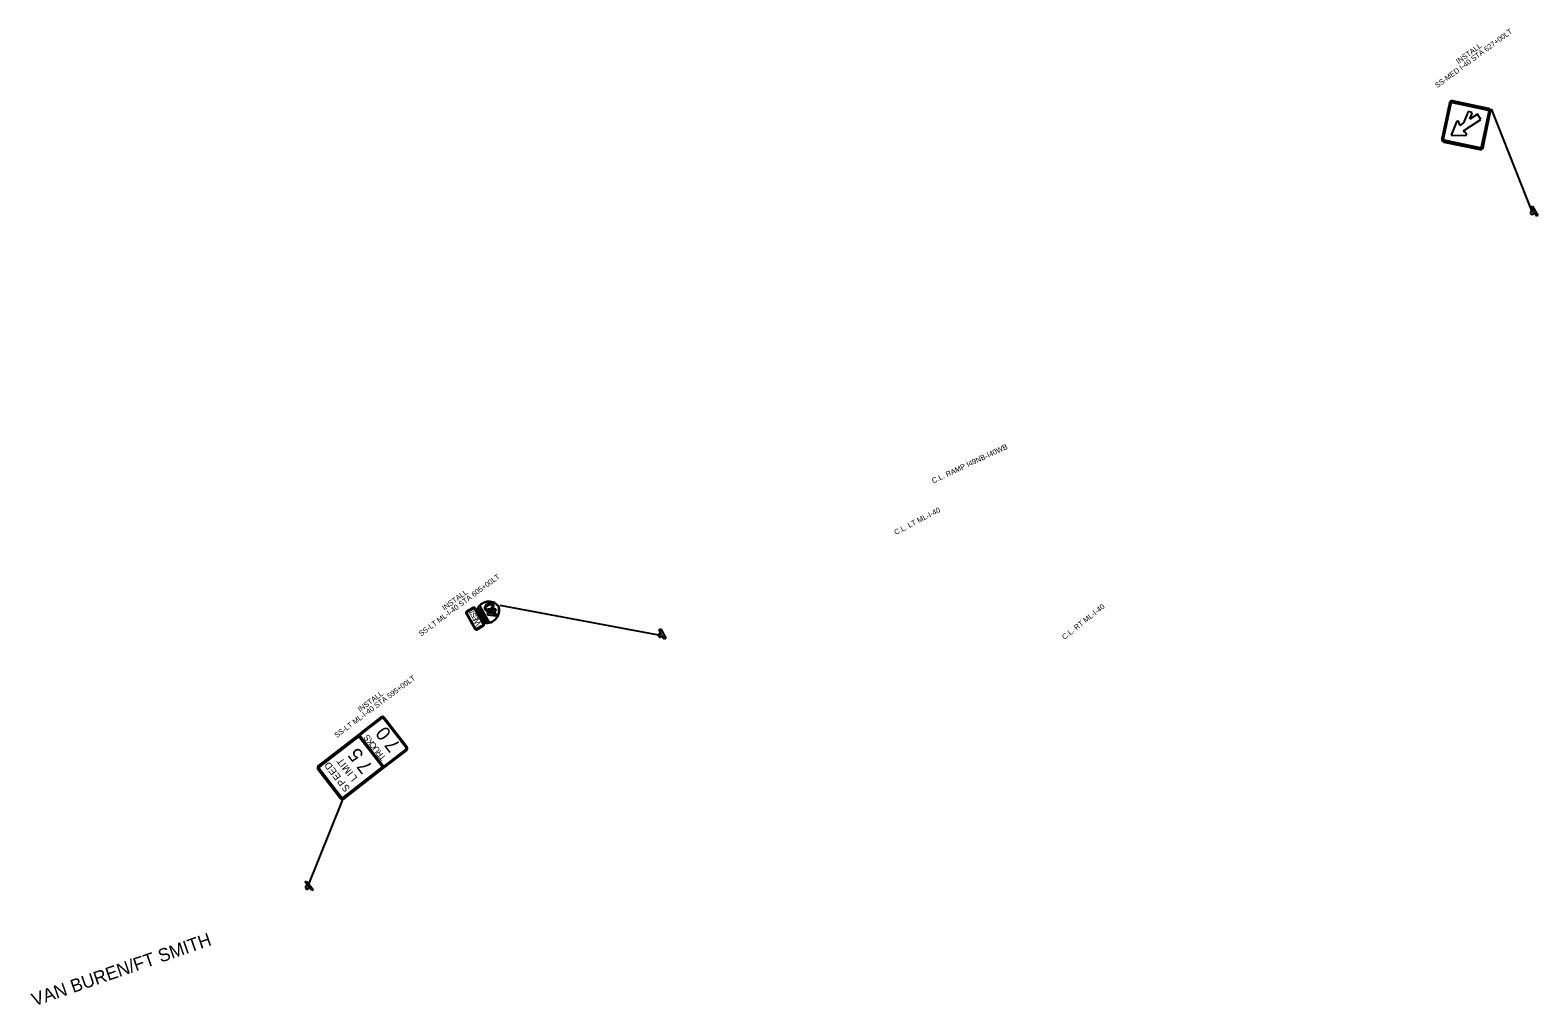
# Model space of a CAD drawing. Extents: x 639753 to 654136, y 407791 to 434220.
# Drawn here: x 639753 to 643194, y 422989 to 425213 of the extents above; entities that cross this region are included whole.
import ezdxf

# ---------------------------------------------------------------- set-up
doc = ezdxf.new("R2010")
doc.units = 0
for name, color, linetype in [('C-TRAF-SYMB', 7, 'Continuous'), ('R_Anno_Text', 7, 'Continuous'), ('R_Dimension', 7, 'Continuous'), ('S_SIGN', 7, 'Continuous')]:
    doc.layers.add(name, color=color, linetype=linetype)

msp = doc.modelspace()

# ---------------------------------------------------------------- linework, layer by layer
at = {"layer": 'C-TRAF-SYMB'}
for p, q in [((643178.4, 424809.3), (643181.8, 424811.3)), ((643183.9, 424799.8), (643178.4, 424809.3)), ((643181.8, 424811.3), (643193.9, 424790.6)), ((643183.8, 424799.7), (643183.9, 424799.8)), ((643190.5, 424788.6), (643184.8, 424798.2)), ((643184.8, 424798.2), (643184.8, 424798.2)), ((643193.9, 424790.6), (643190.5, 424788.6)), ((641188.4, 423844.7), (641191.9, 423846.7)), ((641193.8, 423835.1), (641188.4, 423844.7)), ((641191.9, 423846.7), (641203.6, 423825.7)), ((641193.7, 423835), (641193.8, 423835.1)), ((641194.7, 423833.5), (641194.6, 423833.5)), ((641200.1, 423823.8), (641194.7, 423833.5)), ((641203.6, 423825.7), (641200.1, 423823.8)), ((640380.5, 423268.7), (640383.7, 423271.2)), ((640387.4, 423260), (640380.5, 423268.7)), ((640383.7, 423271.2), (640398.5, 423252.3)), ((640387.3, 423259.9), (640387.4, 423260)), ((640388.5, 423258.6), (640388.4, 423258.5)), ((640395.3, 423249.8), (640388.5, 423258.6)), ((640398.5, 423252.3), (640395.3, 423249.8))]:
    msp.add_line(p, q, dxfattribs=at)
for centre, start, end in [((643181, 424796.9), 120.2947, 17.9748), ((643181, 424796.9), 44.1568, 120.2947), ((641190.8, 423832.3), 119.2135, 16.8936), ((641190.8, 423832.3), 43.0756, 119.2135), ((640384.8, 423256.8), 128.0671, 25.7472), ((640384.8, 423256.8), 51.9292, 128.0671)]:
    msp.add_arc(centre, 4, start, end, dxfattribs=at)
at = {"layer": 'R_Dimension'}
for p, q in [((643087.3, 425033.5), (643181, 424796.9)), ((640824.5, 423900.7), (641190.8, 423832.3)), ((640464.4, 423455.4), (640384.8, 423256.8))]:
    msp.add_line(p, q, dxfattribs=at)
at = {"layer": 'S_SIGN'}
for p, q in [((642992.1, 425047.4), (642974.8, 424965.2)), ((643081.4, 425034.7), (642999.3, 425052)), ((643008.6, 425004), (642996.1, 424974)), ((643016.3, 424995.5), (643013.8, 425003.7)), ((643024, 424983.8), (643063.6, 425009.6)), ((643043.9, 425025.5), (643034.6, 425027.5)), ((643056, 425021.4), (643039, 425010.3)), ((643063.6, 425009.6), (643056, 425021.4)), ((643068.8, 424945.4), (643086.1, 425027.6)), ((642996.1, 424974), (643028.6, 424973.3)), ((643017.8, 424996.5), (643016.3, 424995.5)), ((643030.4, 424978.2), (643024, 424983.8)), ((642979.5, 424958.1), (643061.7, 424940.8)), ((640747.2, 423882.9), (640767.7, 423846.2)), ((640764.1, 423895.7), (640748.4, 423886.9)), ((640788.7, 423857.9), (640768.2, 423894.6)), ((640778.6, 423899.5), (640799.8, 423861.6)), ((640800.8, 423861.8), (640779.3, 423900.2)), ((640771.8, 423845), (640787.5, 423853.8))]:
    msp.add_line(p, q, dxfattribs=at)
for points in [[(642993.6, 425047.1), (642976.3, 424964.9)], [(642978.7, 424964.4), (642996.1, 425046.6)], [(642993.6, 425047.1), (642993.6, 425047.1), (642993.6, 425047.1)], [(642998.4, 425048.1), (643080.6, 425030.8)], [(643081.1, 425033.2), (642998.9, 425050.5)], [(643082.2, 425028.4), (643064.9, 424946.2)], [(643067.3, 424945.7), (643084.6, 425027.9)], [(643081.1, 425033.2), (643081.1, 425033.2), (643081.1, 425033.2)], [(642979.8, 424959.5), (643062, 424942.2)], [(642979.8, 424959.5), (642979.8, 424959.5), (642979.8, 424959.5)], [(643062.5, 424944.7), (642980.3, 424962)], [(643067.3, 424945.7), (643067.3, 424945.7), (643067.3, 424945.7)], [(640796.4, 423903.4), (640793.8, 423901.7), (640791.6, 423899.7), (640790.3, 423897.8), (640789.7, 423895.7), (640789.8, 423893.4), (640790.6, 423891.3), (640792, 423889.5), (640793.8, 423888.3), (640796, 423887.7), (640798.2, 423887.8), (640801.1, 423888.7), (640803.9, 423890), (640806.5, 423891.7), (640808.8, 423893.7), (640810, 423895.6), (640810.6, 423897.7), (640810.6, 423899.9), (640809.8, 423902.1), (640808.4, 423903.8), (640806.5, 423905.1), (640804.4, 423905.7), (640802.2, 423905.6), (640799.3, 423904.7), (640796.4, 423903.4)], [(640792, 423889.5), (640793.8, 423888.3), (640796, 423887.7), (640798.2, 423887.8), (640801.1, 423888.7), (640803.9, 423890), (640806.5, 423891.7), (640808.8, 423893.7), (640810, 423895.6), (640810.6, 423897.7), (640810.6, 423899.9), (640809.8, 423902.1), (640808.4, 423903.8), (640806.5, 423905.1), (640804.4, 423905.7), (640802.2, 423905.6), (640799.3, 423904.7), (640796.4, 423903.4), (640793.8, 423901.7), (640791.6, 423899.7), (640790.3, 423897.8), (640789.7, 423895.7), (640789.8, 423893.4), (640790.6, 423891.3), (640792, 423889.5)], [(640798.1, 423900.5), (640800.5, 423901.6), (640802.9, 423902.3), (640804.1, 423902.4), (640805.2, 423902.1), (640806.2, 423901.4), (640806.9, 423900.5), (640807.3, 423899.5), (640807.4, 423898.6), (640807.2, 423897.6), (640806.8, 423896.7), (640806.1, 423895.7), (640805.1, 423894.8), (640803.9, 423893.8), (640802.3, 423892.9), (640799.9, 423891.8), (640797.4, 423891.1), (640796.3, 423891), (640795.2, 423891.3), (640794.2, 423892), (640793.5, 423893), (640793.1, 423893.9), (640793, 423894.9), (640793.1, 423895.8), (640793.6, 423896.7), (640794.3, 423897.7), (640795.3, 423898.6), (640796.5, 423899.6), (640798.1, 423900.5)], [(640798.1, 423900.5), (640800.5, 423901.6), (640802.9, 423902.3), (640804.1, 423902.4), (640805.2, 423902.1), (640806.2, 423901.4), (640806.9, 423900.5), (640807.3, 423899.5), (640807.4, 423898.6), (640807.2, 423897.6), (640806.8, 423896.7), (640806.1, 423895.7), (640805.1, 423894.8), (640803.9, 423893.8), (640802.3, 423892.9), (640799.9, 423891.8), (640797.4, 423891.1), (640796.3, 423891), (640795.2, 423891.3), (640794.2, 423892), (640793.5, 423893), (640793.1, 423893.9), (640793, 423894.9), (640793.1, 423895.8), (640793.6, 423896.7), (640794.3, 423897.7), (640795.3, 423898.6), (640796.5, 423899.6), (640798.1, 423900.5)], [(640747.9, 423883.2), (640768.4, 423846.6)], [(640747.9, 423883.2), (640747.9, 423883.2), (640747.9, 423883.2)], [(640764.5, 423895.1), (640748.8, 423886.3)], [(640769.5, 423847.2), (640749, 423883.8)], [(640749.4, 423885.2), (640765.1, 423894)], [(640764.5, 423895.1), (640764.5, 423895.1), (640764.5, 423895.1)], [(640766.4, 423893.6), (640786.9, 423856.9)], [(640788, 423857.5), (640767.5, 423894.2)], [(640780.7, 423893.7), (640781.9, 423891.5), (640777.5, 423889), (640776.4, 423891.1), (640777, 423891.5), (640777.8, 423890), (640778.9, 423890.6), (640778.4, 423891.5), (640779, 423891.9), (640779.5, 423890.9), (640780.9, 423891.7), (640780.1, 423893.3), (640780.7, 423893.7)], [(640778.5, 423888.6), (640779, 423887.8), (640782.8, 423890), (640783.1, 423889.3), (640779.3, 423887.2), (640779.7, 423886.4), (640779.2, 423886.1), (640778, 423888.3), (640778.5, 423888.6)], [(640783.7, 423888.3), (640784, 423887.7), (640783, 423886.7), (640783.5, 423885.8), (640784.8, 423886.2), (640785.2, 423885.6), (640780.2, 423884.2), (640779.9, 423884.8), (640783.7, 423888.3)], [(640781.6, 423883.2), (640782, 423882.4), (640785.8, 423884.5), (640786.1, 423883.9), (640782.3, 423881.8), (640782.8, 423881), (640782.2, 423880.7), (640781, 423882.9), (640781.6, 423883.2)], [(640782.5, 423886.2), (640781.4, 423885.2), (640782.8, 423885.6), (640782.5, 423886.2)], [(640787, 423879.3), (640786.7, 423879.9), (640786.8, 423880), (640786.9, 423880.1), (640787, 423880.1), (640787.1, 423880.2), (640787.1, 423880.3), (640787.2, 423880.4), (640787.2, 423880.5), (640787.2, 423880.6), (640787.2, 423880.7), (640787.1, 423880.8), (640787.1, 423880.9), (640787, 423881), (640787, 423881.1), (640786.9, 423881.1), (640786.8, 423881.2), (640786.7, 423881.2), (640786.6, 423881.3), (640786.5, 423881.3), (640786.4, 423881.2), (640786.3, 423881.2), (640786.2, 423881.2), (640786.1, 423881.1), (640786.1, 423881.1), (640786, 423881), (640785.9, 423881), (640785.9, 423880.9), (640785.8, 423880.9), (640785.8, 423880.8), (640785.7, 423880.8), (640785.7, 423880.7), (640785.7, 423880.6), (640785.6, 423880.6), (640785.6, 423880.5), (640785.6, 423880.4), (640785.6, 423880.4), (640785.5, 423880.3), (640785.5, 423880.2), (640785.5, 423880.1), (640785.5, 423880.1), (640785.5, 423879.4), (640785.5, 423879.3), (640785.5, 423879.3), (640785.5, 423879.2), (640785.4, 423879.1), (640785.4, 423879), (640785.4, 423879), (640785.4, 423878.9), (640785.3, 423878.8), (640785.3, 423878.8), (640785.3, 423878.7), (640785.2, 423878.7), (640785.2, 423878.6), (640785.1, 423878.5), (640785, 423878.5), (640785, 423878.5), (640784.9, 423878.4), (640784.9, 423878.4), (640784.7, 423878.3), (640784.6, 423878.3), (640784.5, 423878.2), (640784.4, 423878.2), (640784.3, 423878.2), (640784.2, 423878.2), (640784.1, 423878.2), (640784, 423878.2), (640783.9, 423878.3), (640783.8, 423878.3), (640783.7, 423878.3), (640783.6, 423878.4), (640783.5, 423878.4), (640783.4, 423878.5), (640783.4, 423878.6), (640783.3, 423878.7), (640783.2, 423878.8), (640783.2, 423878.8), (640783.1, 423879), (640783.1, 423879.1), (640783, 423879.2), (640783, 423879.3), (640783, 423879.4), (640783, 423879.5), (640783, 423879.6), (640783, 423879.7), (640783, 423879.8), (640783.1, 423879.9), (640783.1, 423880), (640783.2, 423880.1), (640783.2, 423880.2), (640783.3, 423880.3), (640783.4, 423880.4), (640783.4, 423880.4), (640783.5, 423880.5), (640783.6, 423880.6), (640784, 423879.9), (640783.9, 423879.9), (640783.8, 423879.8), (640783.8, 423879.7), (640783.7, 423879.6)], [(640783.7, 423879.6), (640783.7, 423879.5), (640783.7, 423879.4), (640783.7, 423879.3), (640783.8, 423879.2), (640783.8, 423879.1), (640783.9, 423879), (640784, 423879), (640784.1, 423878.9), (640784.2, 423878.9), (640784.3, 423878.9), (640784.4, 423878.9), (640784.5, 423879), (640784.6, 423879), (640784.6, 423879.1), (640784.7, 423879.1), (640784.7, 423879.2), (640784.8, 423879.3), (640784.8, 423879.4), (640784.8, 423879.4), (640784.8, 423880.1), (640784.8, 423880.2), (640784.8, 423880.4), (640784.9, 423880.6), (640784.9, 423880.7), (640785, 423880.9), (640785.1, 423881.1), (640785.2, 423881.2), (640785.3, 423881.3), (640785.4, 423881.4), (640785.5, 423881.5), (640785.6, 423881.6), (640785.7, 423881.7), (640785.8, 423881.8), (640785.9, 423881.8), (640786, 423881.9), (640786.1, 423881.9), (640786.2, 423881.9), (640786.4, 423882), (640786.5, 423882), (640786.6, 423882), (640786.7, 423882), (640786.8, 423881.9), (640786.9, 423881.9), (640787, 423881.9), (640787.1, 423881.8), (640787.2, 423881.8), (640787.3, 423881.7), (640787.4, 423881.7), (640787.4, 423881.6), (640787.5, 423881.5), (640787.6, 423881.4), (640787.6, 423881.4), (640787.7, 423881.3), (640787.8, 423881.2), (640787.8, 423881.1), (640787.8, 423881), (640787.9, 423880.9), (640787.9, 423880.8), (640787.9, 423880.6), (640787.9, 423880.5), (640787.9, 423880.4), (640787.9, 423880.3), (640787.8, 423880.2), (640787.8, 423880.1), (640787.8, 423880), (640787.7, 423879.9), (640787.7, 423879.8), (640787.6, 423879.7), (640787.5, 423879.7), (640787.4, 423879.6), (640787.4, 423879.5), (640787.3, 423879.5), (640787.2, 423879.4), (640787, 423879.3)], [(640788.7, 423879.3), (640789.1, 423878.7), (640787.4, 423876.9), (640787.7, 423876.4), (640789.7, 423877.5), (640790, 423876.9), (640785.7, 423874.5), (640784.9, 423875.8), (640784.9, 423875.9), (640784.8, 423876.1), (640784.8, 423876.2), (640784.8, 423876.3), (640784.8, 423876.4), (640784.8, 423876.6), (640784.8, 423876.7), (640784.9, 423876.8), (640784.9, 423876.9), (640785, 423877), (640785.1, 423877.1), (640785.1, 423877.2), (640785.3, 423877.4), (640785.5, 423877.5), (640785.7, 423877.6), (640785.9, 423877.7), (640786, 423877.7), (640786.1, 423877.7), (640786.2, 423877.7), (640786.3, 423877.7), (640786.4, 423877.7), (640786.5, 423877.7), (640786.6, 423877.7), (640786.7, 423877.6), (640786.8, 423877.6), (640786.8, 423877.5), (640786.9, 423877.5), (640788.7, 423879.3)], [(640787.1, 423876), (640786.6, 423876.8), (640786.5, 423876.9), (640786.4, 423877), (640786.3, 423877), (640786.1, 423877), (640786, 423876.9), (640785.9, 423876.9), (640785.7, 423876.8), (640785.6, 423876.7), (640785.6, 423876.7), (640785.5, 423876.6), (640785.5, 423876.6), (640785.5, 423876.5), (640785.5, 423876.5), (640785.5, 423876.4), (640785.5, 423876.3), (640785.5, 423876.3), (640785.5, 423876.2), (640785.5, 423876.2), (640786, 423875.4), (640787.1, 423876)], [(640790.5, 423876.2), (640791.7, 423874), (640787.3, 423871.5), (640786.1, 423873.7), (640786.8, 423874), (640787.6, 423872.5), (640788.7, 423873.1), (640788.2, 423874), (640788.8, 423874.4), (640789.3, 423873.5), (640790.7, 423874.3), (640789.8, 423875.8), (640790.5, 423876.2)], [(640788.3, 423871.1), (640788.7, 423870.4), (640792.5, 423872.5), (640792.9, 423871.9), (640789.1, 423869.7), (640789.5, 423869), (640788.9, 423868.6), (640787.7, 423870.8), (640788.3, 423871.1)], [(640793.7, 423870.3), (640794, 423869.9), (640791.8, 423866.9), (640794.7, 423868.6), (640795.1, 423867.9), (640790.7, 423865.5), (640790.3, 423866.1), (640792.3, 423868.7), (640789.7, 423867.3), (640789.4, 423867.9), (640793.7, 423870.3)], [(640795.6, 423867), (640795.9, 423866.4), (640791.6, 423864), (640791.2, 423864.6), (640795.6, 423867)], [(640809.3, 423891.9), (640806.4, 423890.3), (640807.3, 423888.6), (640795.7, 423882.1), (640797.4, 423879.2), (640815.3, 423876.9), (640817.1, 423877.9), (640811.8, 423887.3), (640816.6, 423890), (640814.9, 423892.9), (640810.2, 423890.2), (640809.3, 423891.9)], [(640795.7, 423882.1), (640797.4, 423879.2), (640815.3, 423876.9), (640817.1, 423877.9), (640811.8, 423887.3), (640816.6, 423890), (640814.9, 423892.9), (640810.2, 423890.2), (640809.3, 423891.9), (640806.4, 423890.3), (640807.3, 423888.6), (640795.7, 423882.1)], [(640808.9, 423885.7), (640811.7, 423880.7), (640802.2, 423882), (640808.9, 423885.7)], [(640808.9, 423885.7), (640811.7, 423880.7), (640802.2, 423882), (640808.9, 423885.7)], [(640786.6, 423855.6), (640770.8, 423846.8)], [(640771.5, 423845.7), (640787.2, 423854.5)], [(640771.5, 423845.7), (640771.5, 423845.7), (640771.5, 423845.7)], [(640788, 423857.5), (640788, 423857.5), (640788, 423857.5)], [(640553.3, 423645.6), (640519.5, 423619.4)], [(640520.3, 423618.5), (640554.1, 423644.6)], [(640555.2, 423643.2), (640521.4, 423617)], [(640555.2, 423643.2), (640555.2, 423643.2), (640555.2, 423643.2)], [(640610.7, 423575.2), (640558.3, 423642.8)], [(640559.8, 423643.9), (640612.1, 423576.3)], [(640613, 423577), (640560.7, 423644.6)], [(640500.6, 423604.7), (640410.4, 423534.9)], [(640411.3, 423533.8), (640501.5, 423603.5)], [(640503, 423601.6), (640412.9, 423531.8)], [(640519.5, 423619.4), (640500.6, 423604.7), (640559.3, 423528.8), (640578.3, 423543.5), (640578.3, 423543.5), (640578.3, 423543.5)], [(640503.3, 423603.1), (640502.2, 423604.5), (640503.7, 423605.6), (640503.7, 423605.6), (640503.7, 423605.6)], [(640503, 423601.6), (640503, 423601.6), (640503, 423601.6)], [(640558.4, 423531.9), (640503.3, 423603.1)], [(640503.7, 423605.6), (640520.3, 423618.5)], [(640521.4, 423617), (640504.8, 423604.2)], [(640504.8, 423604.2), (640559.9, 423533)], [(640504.8, 423604.2), (640504.8, 423604.2), (640504.8, 423604.2)], [(640521.4, 423617), (640521.4, 423617), (640521.4, 423617)], [(640576.5, 423545.9), (640610.3, 423572)], [(640611.4, 423570.6), (640577.6, 423544.4)], [(640578.3, 423543.5), (640612.1, 423569.7)], [(640610.7, 423575.2), (640610.7, 423575.2), (640610.7, 423575.2)], [(640613, 423577), (640613, 423577), (640613, 423577)], [(640409.3, 423526.5), (640460.8, 423460.1)], [(640461.9, 423461), (640410.5, 423527.4)], [(640412.5, 423529), (640463.9, 423462.5)], [(640412.5, 423529), (640412.5, 423529), (640412.5, 423529)], [(640466.7, 423462.2), (640556.9, 423532)], [(640558.4, 423530), (640468.3, 423460.2)], [(640469.2, 423459), (640559.3, 423528.8), (640559.3, 423528.8), (640559.3, 423528.8)], [(640561, 423531.6), (640559.5, 423530.5), (640558.4, 423531.9), (640558.4, 423531.9), (640558.4, 423531.9)], [(640559.9, 423533), (640576.5, 423545.9)], [(640559.9, 423533), (640559.9, 423533), (640559.9, 423533)], [(640577.6, 423544.4), (640561, 423531.6)], [(640576.5, 423545.9), (640576.5, 423545.9), (640576.5, 423545.9)], [(640466.7, 423462.2), (640466.7, 423462.2), (640466.7, 423462.2)]]:
    msp.add_lwpolyline(points, dxfattribs=at)
for centre, radius, start, end in [((642998, 425046.1), 6, 78.1077, 168.1073), ((642998, 425046.1), 4.5, 78.1077, 168.1073), ((642998, 425046.1), 2, 78.1077, 168.1073), ((643011.1, 425002.9), 2.75, 17.459, 157.3667), ((643003.4, 425018.4), 26.2, 303.4385, 331.6905), ((642947, 425048.2), 90, 332.0217, 346.6865), ((642947, 425048.2), 99.5, 337.6327, 346.8223), ((643080.2, 425028.8), 2, 348.1075, 78.1077), ((643080.2, 425028.8), 4.5, 348.1075, 78.1077), ((643080.2, 425028.8), 6, 348.1075, 78.1077), ((643028.6, 424976.1), 2.75, 268.8479, 48.7562), ((642980.7, 424963.9), 6, 168.1075, 258.1073), ((642980.7, 424963.9), 4.5, 168.1075, 258.1073), ((642980.7, 424963.9), 2, 168.1075, 258.1073), ((643062.9, 424946.6), 6, 258.1073, 348.1075), ((643062.9, 424946.6), 4.5, 258.1073, 348.1075), ((643062.9, 424946.6), 2, 258.1073, 348.1075), ((640799.6, 423879.5), 30, 40.7506, 157.5446), ((640799.6, 423879.5), 29, 41.1431, 134.4601), ((640749.9, 423884.3), 3, 119.2135, 209.2137), ((640749.9, 423884.3), 2.25, 119.2135, 209.2137), ((640749.9, 423884.3), 1, 119.2135, 209.2137), ((640765.6, 423893.1), 3, 29.2135, 119.2137), ((640765.6, 423893.1), 2.25, 29.2135, 119.2137), ((640765.6, 423893.1), 1, 29.2135, 119.2137), ((640751.1, 423869.3), 30, 12.2225, 46.2046), ((640799.6, 423879.5), 29, 136.4767, 156.2176), ((640751.1, 423869.4), 31, 12.639, 44.7745), ((640759.7, 423854), 30, 12.2225, 46.2046), ((640759.7, 423853.9), 31, 13.6526, 45.788), ((640793.8, 423890), 30, 260.8824, 17.6764), ((640793.8, 423890), 29, 283.9669, 17.284), ((640770.4, 423847.7), 3, 209.2137, 299.2133), ((640770.4, 423847.7), 2.25, 209.2137, 299.2133), ((640770.4, 423847.7), 1, 209.2137, 299.2133), ((640786.1, 423856.4), 1, 299.2133, 29.2135), ((640786.1, 423856.4), 2.25, 299.2133, 29.2135), ((640786.1, 423856.4), 3, 299.2133, 29.2135), ((640793.8, 423890), 29, 262.2094, 281.9501), ((640556.6, 423641.4), 5.26, 37.743, 127.7432), ((640556.6, 423641.4), 4.06, 37.743, 127.7432), ((640556.6, 423641.4), 2.26, 37.743, 127.7432), ((640608.9, 423573.8), 2.26, 307.7428, 37.743), ((640608.9, 423573.8), 4.06, 307.7428, 37.743), ((640608.9, 423573.8), 5.26, 307.7428, 37.743), ((640414.1, 423530.2), 6, 127.743, 217.7432), ((640414.1, 423530.2), 4.5, 127.743, 217.7432), ((640414.1, 423530.2), 2, 127.743, 217.7432), ((640465.5, 423463.8), 6, 217.7432, 307.7428), ((640465.5, 423463.8), 4.5, 217.7432, 307.7428), ((640465.5, 423463.8), 2, 217.7432, 307.7428)]:
    msp.add_arc(centre, radius, start, end, dxfattribs=at)

# ---------------------------------------------------------------- texts
at = {"layer": 'R_Anno_Text'}
for s, rotation, p in [('SS-MED I-40 STA 627+00LT', 36.3915, (642964.6, 425080.9)), ('INSTALL', 36.3915, (643012.7, 425135.5)), ('C.L. RAMP I49NB-I40WB', 25.0796, (641814, 424178.7)), ('C.L. LT ML-I-40', 27.3801, (641728.4, 424061.1)), ('SS-LT ML-I-40 STA 605+00LT', 36.5549, (640645, 423829.5)), ('INSTALL', 36.5549, (640698.5, 423888.3)), ('C.L. RT ML-I-40', 38.422, (642113.5, 423821.8)), ('SS-LT ML-I-40 STA 595+00LT', 36.6902, (640452.4, 423597.6)), ('INSTALL', 36.6902, (640505.7, 423656.6))]:
    msp.add_text(s, height=12, rotation=rotation, dxfattribs=at).set_placement(p)
at = {"layer": 'S_SIGN'}
for s, height, rotation, p in [('T', 12, 119.2135, (640768.4, 423884)), ('S', 12, 119.2135, (640772.6, 423876.5)), ('E', 12, 119.2135, (640776.5, 423869.5)), ('W', 14, 119.2135, (640782.7, 423858.4)), ('S', 14, 127.743, (640531.4, 423597.5)), ('K', 14, 127.743, (640538.4, 423588.5)), ('0', 32, 127.743, (640578.5, 423608.5)), ('5', 32, 127.743, (640515.3, 423559.6)), ('C', 14, 127.743, (640545.3, 423579.6)), ('U', 14, 127.743, (640552.4, 423570.4)), ('R', 14, 127.743, (640559.5, 423561.2)), ('T', 14, 127.743, (640565.8, 423553.1)), ('7', 32, 127.743, (640599.4, 423581.6)), ('D', 16, 127.743, (640444.7, 423533.1)), ('E', 16, 127.743, (640453.9, 423521.2)), ('T', 16, 127.743, (640471.8, 423543.9)), ('I', 16, 127.743, (640475.5, 423539.1)), ('M', 16, 127.743, (640487, 423524.2)), ('7', 32, 127.743, (640536.1, 423532.6)), ('E', 16, 127.743, (640463.1, 423509.3)), ('P', 16, 127.743, (640473.5, 423496)), ('S', 16, 127.743, (640483.8, 423482.6)), ('I', 16, 127.743, (640491.2, 423518.8)), ('L', 16, 127.743, (640500.4, 423506.9)), ('VAN BUREN/FT SMITH', 30, 19.061, (639762.2, 422985.2))]:
    msp.add_text(s, height=height, rotation=rotation, dxfattribs=at).set_placement(p)

doc.saveas('drawing.dxf')
